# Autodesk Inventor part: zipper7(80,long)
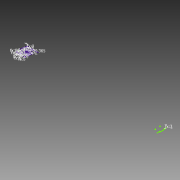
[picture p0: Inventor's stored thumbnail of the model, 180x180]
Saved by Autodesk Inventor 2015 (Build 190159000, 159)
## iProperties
Created: 2015-02
Part Number: zipper7(80,long)
Material: Generic
Document SubType Name: Modeling
Designer: sungeun
Density: 1 g/cm^3
Appearance: Default
Author: sungeun
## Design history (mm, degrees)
sketch "Sketch1"
  geometry: L1 (0, 2)-(8.682, 51.24); L2 (8.682, 51.24)-(14.682, 51.24); L3 (14.682, 51.24)-(23.365, 2); L4 (23.365, 2)-(29.365, 2); L5 (29.365, 0)-(0, 0); L6 (8.682, 38.62)-(14.682, 38.62); L7 (14.682, 38.62)-(14.682, 14.62); L8 (14.682, 14.62)-(8.682, 14.62); L9 (8.682, 14.62)-(8.682, 38.62); L10 (23.365, 38.62)-(29.365, 38.62); L11 (29.365, 38.62)-(29.365, 14.62); L12 (29.365, 14.62)-(23.365, 14.62); L13 (23.365, 14.62)-(23.365, 38.62); L14 (11.682, 53.24)-(41.047, 53.24); L15 (0, 2)-(-3, 2); L16 (-3, 2)-(-3, 15.209); L17 (-3, 15.209)-(0, 15.209); L18 (0, 15.209)-(0, 38.62); L19 (0, 38.62)-(-3, 38.62); L20 (-3, 38.62)-(-3, 53.24); L21 (-3, 53.24)-(11.682, 53.24); L22 (-3, 2)-(-6, 2); L23 (-6, 2)-(-14.682, 51.24); L24 (-14.682, 51.24)-(-17.682, 51.24); L25 (-17.682, 51.24)-(-17.682, 38.62); L26 (-17.682, 0)-(-17.682, 15.209); L27 (0, 0)-(-17.682, 0); L28 (-3, 53.24)-(-17.682, 53.24); L29 (-17.682, 38.62)-(-20.682, 38.62); L30 (-20.682, 38.62)-(-20.682, 15.209); L31 (-20.682, 15.209)-(-17.682, 15.209); L32 (-17.682, 53.24)-(-17.682, 51.24); L33 (689.365, 50.063)-(689.365, 38.032); L34 (689.365, 38.032)-(692.365, 38.032); L35 (692.365, 38.032)-(692.365, 14.032); L36 (692.365, 14.032)-(689.365, 14.032); L37 (689.365, 14.032)-(689.365, 0); 13 further points
  constraints: 74 end point, 14 perpendicular, 11 midpoint, 8 point on line, 7 horizontal alignment, 6 horizontal, 6 parallel, 6 vertical alignment, 2 equal length, 2 vertical
  dimensions: "d0" = 2 distance of L5.end L1.start; "d1" = 6 distance of L1.end L2.end; "d2" = 80 deg angle of L5 L1; "d4" = 2 distance between parallel lines of L5 L4 (= d0); "d34" = 6 distance of L3.end L4.end (= d1); "d35" = 23.36482 distance of L1.start L3.end (derived); "d36" = 50 distance of L1.start L1.end; "d44" = 6 distance of L7.end L8.end (= d1); "d45" = 24 distance of L8.end L6.start (= 4 x d1); "d46" = 6 distance of L11.end L12.end (= d1); "d47" = 24 distance of L12.end L10.start (= d45); "d55" = 2 distance between parallel lines of L2 L14 (= d4); "d56" = 29.36482 distance of L14.start L14.end (= d35 + d46); "d64" = 3 distance of L1.start L15.end (= 0.5 x d1); "d65" = 3 distance of L15.end L22.end (= 0.5 x d1); "d66" = 80 deg angle of L27 L23 (= d2); "d67" = 3 distance of L23.end L24.end (= 0.5 x d1); "d69" = 3 distance of L18.end L19.end (= d68); "d80" = 3 distance of L30.end L26.end (= d67); "d99" = 3 distance of L33.end L34.end (derived)
other parameters: "d6" = 56.39702 (derived), "d68" = 3 (= d67)
